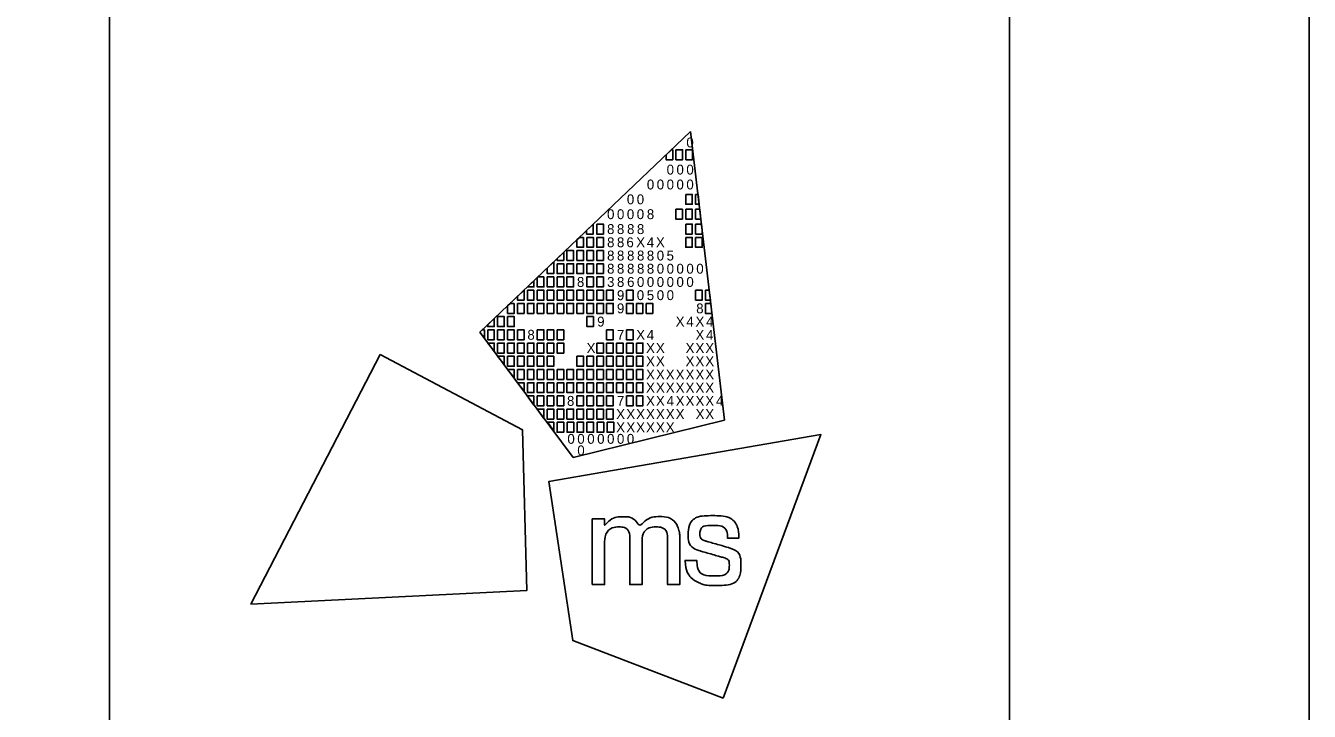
# Model space of a CAD drawing. Extents: x -0.2 to 34, y -2 to 20.
# Drawn here: x 31.86 to 34, y 1.115 to 2.258 of the extents above; entities that cross this region are included whole.
import ezdxf

# ---------------------------------------------------------------- set-up
doc = ezdxf.new("R2010")
doc.units = 0
for name, color, linetype in [('SH_Border', 7, 'Continuous'), ('SH_Cut_Line', 7, 'Continuous'), ('SH_Data', 7, 'Continuous')]:
    doc.layers.add(name, color=color, linetype=linetype)

msp = doc.modelspace()

# ---------------------------------------------------------------- linework, layer by layer
at = {"layer": 'SH_Border'}
msp.add_line((32, -1.5048), (32, 19.4952), dxfattribs=at)
msp.add_lwpolyline([(1.5, 19.4952), (33.5, 19.4952), (33.5, -1.5048), (1.5, -1.5048)], close=True, dxfattribs=at)
at = {"layer": 'SH_Cut_Line'}
msp.add_lwpolyline([(0, -2.0048), (34, -2.0048), (34, 19.9952), (0, 19.9952)], close=True, dxfattribs=at)
at = {"layer": 'SH_Data'}
for p, q in [((32.6175, 1.7471), (32.9688, 2.0813)), ((32.9688, 2.0813), (32.9688, 2.0813)), ((32.9688, 2.0813), (33.0253, 1.6004)), ((32.773, 1.5382), (32.6175, 1.7471)), ((33.0253, 1.6004), (32.773, 1.5382)), ((32.75, 1.4952), (32.75, 1.4952))]:
    msp.add_line(p, q, dxfattribs=at)
for points in [[(32.9279, 2.0424), (32.9369, 2.051), (32.9389, 2.051), (32.9389, 2.0345), (32.9279, 2.0345)], [(32.9444, 2.051), (32.9554, 2.051), (32.9554, 2.0345), (32.9444, 2.0345)], [(32.9609, 2.051), (32.9719, 2.051), (32.9719, 2.0345), (32.9609, 2.0345)], [(32.9606, 1.9767), (32.9716, 1.9767), (32.9716, 1.9602), (32.9606, 1.9602)], [(32.9771, 1.9767), (32.9811, 1.9767), (32.983, 1.9602), (32.9771, 1.9602)], [(32.9441, 1.9519), (32.9551, 1.9519), (32.9551, 1.9354), (32.9441, 1.9354)], [(32.9606, 1.9519), (32.9716, 1.9519), (32.9716, 1.9354), (32.9606, 1.9354)], [(32.9771, 1.9519), (32.984, 1.9519), (32.9859, 1.9354), (32.9771, 1.9354)], [(32.7953, 1.9163), (32.8064, 1.9268), (32.8064, 1.9106), (32.7953, 1.9106)], [(32.8123, 1.9271), (32.8233, 1.9271), (32.8233, 1.9106), (32.8123, 1.9106)], [(32.9606, 1.9271), (32.9716, 1.9271), (32.9716, 1.9106), (32.9606, 1.9106)], [(32.9771, 1.9271), (32.9869, 1.9271), (32.9881, 1.917), (32.9881, 1.9106), (32.9771, 1.9106)], [(32.7958, 1.9051), (32.8068, 1.9051), (32.8068, 1.8886), (32.7958, 1.8886)], [(32.8123, 1.9051), (32.8233, 1.9051), (32.8233, 1.8886), (32.8123, 1.8886)], [(32.9606, 1.9051), (32.9716, 1.9051), (32.9716, 1.8886), (32.9606, 1.8886)], [(32.9771, 1.9051), (32.9881, 1.9051), (32.9881, 1.8886), (32.9771, 1.8886)], [(32.7627, 1.8831), (32.7737, 1.8831), (32.7737, 1.8666), (32.7627, 1.8666)], [(32.7793, 1.8831), (32.7903, 1.8831), (32.7903, 1.8666), (32.7793, 1.8666)], [(32.7958, 1.8831), (32.8068, 1.8831), (32.8068, 1.8666), (32.7958, 1.8666)], [(32.8123, 1.8831), (32.8233, 1.8831), (32.8233, 1.8666), (32.8123, 1.8666)], [(32.7462, 1.8611), (32.7572, 1.8611), (32.7572, 1.8446), (32.7462, 1.8446)], [(32.7627, 1.8611), (32.7737, 1.8611), (32.7737, 1.8446), (32.7627, 1.8446)], [(32.7793, 1.8611), (32.7903, 1.8611), (32.7903, 1.8446), (32.7793, 1.8446)], [(32.7958, 1.8611), (32.8068, 1.8611), (32.8068, 1.8446), (32.7958, 1.8446)], [(32.8123, 1.8611), (32.8233, 1.8611), (32.8233, 1.8446), (32.8123, 1.8446)], [(32.7297, 1.8391), (32.7407, 1.8391), (32.7407, 1.8225), (32.7297, 1.8225)], [(32.7462, 1.8391), (32.7572, 1.8391), (32.7572, 1.8225), (32.7462, 1.8225)], [(32.7627, 1.8391), (32.7737, 1.8391), (32.7737, 1.8225), (32.7627, 1.8225)], [(32.7958, 1.8391), (32.8068, 1.8391), (32.8068, 1.8225), (32.7958, 1.8225)], [(32.8123, 1.8391), (32.8233, 1.8391), (32.8233, 1.8225), (32.8123, 1.8225)], [(32.6967, 1.817), (32.7077, 1.817), (32.7077, 1.8005), (32.6967, 1.8005)], [(32.7132, 1.817), (32.7242, 1.817), (32.7242, 1.8005), (32.7132, 1.8005)], [(32.7297, 1.817), (32.7407, 1.817), (32.7407, 1.8005), (32.7297, 1.8005)], [(32.7462, 1.817), (32.7572, 1.817), (32.7572, 1.8005), (32.7462, 1.8005)], [(32.7627, 1.817), (32.7737, 1.817), (32.7737, 1.8005), (32.7627, 1.8005)], [(32.7793, 1.817), (32.7903, 1.817), (32.7903, 1.8005), (32.7793, 1.8005)], [(32.7958, 1.817), (32.8068, 1.817), (32.8068, 1.8005), (32.7958, 1.8005)], [(32.8123, 1.817), (32.8233, 1.817), (32.8233, 1.8005), (32.8123, 1.8005)], [(32.8288, 1.817), (32.8398, 1.817), (32.8398, 1.8005), (32.8288, 1.8005)], [(32.8618, 1.817), (32.8728, 1.817), (32.8728, 1.8005), (32.8618, 1.8005)], [(32.9771, 1.817), (32.9881, 1.817), (32.9881, 1.8005), (32.9771, 1.8005)], [(32.9935, 1.817), (32.9998, 1.817), (33.0018, 1.8005), (32.9935, 1.8005)], [(32.6802, 1.795), (32.6912, 1.795), (32.6912, 1.7785), (32.6802, 1.7785)], [(32.6967, 1.795), (32.7077, 1.795), (32.7077, 1.7785), (32.6967, 1.7785)], [(32.7132, 1.795), (32.7242, 1.795), (32.7242, 1.7785), (32.7132, 1.7785)], [(32.7297, 1.795), (32.7407, 1.795), (32.7407, 1.7785), (32.7297, 1.7785)], [(32.7462, 1.795), (32.7572, 1.795), (32.7572, 1.7785), (32.7462, 1.7785)], [(32.7627, 1.795), (32.7737, 1.795), (32.7737, 1.7785), (32.7627, 1.7785)], [(32.7793, 1.795), (32.7903, 1.795), (32.7903, 1.7785), (32.7793, 1.7785)], [(32.7958, 1.795), (32.8068, 1.795), (32.8068, 1.7785), (32.7958, 1.7785)], [(32.8123, 1.795), (32.8233, 1.795), (32.8233, 1.7785), (32.8123, 1.7785)], [(32.8288, 1.795), (32.8398, 1.795), (32.8398, 1.7785), (32.8288, 1.7785)], [(32.8618, 1.795), (32.8728, 1.795), (32.8728, 1.7785), (32.8618, 1.7785)], [(32.8783, 1.795), (32.8893, 1.795), (32.8893, 1.7785), (32.8783, 1.7785)], [(32.8947, 1.795), (32.9057, 1.795), (32.9057, 1.7785), (32.8947, 1.7785)], [(32.9935, 1.795), (33.0024, 1.795), (33.0044, 1.7785), (32.9935, 1.7785)], [(32.6471, 1.773), (32.6581, 1.773), (32.6581, 1.7565), (32.6471, 1.7565)], [(32.6637, 1.773), (32.6747, 1.773), (32.6747, 1.7565), (32.6637, 1.7565)], [(32.7958, 1.773), (32.8068, 1.773), (32.8068, 1.7565), (32.7958, 1.7565)], [(32.6306, 1.751), (32.6416, 1.751), (32.6416, 1.7345), (32.6306, 1.7345)], [(32.6471, 1.751), (32.6581, 1.751), (32.6581, 1.7345), (32.6471, 1.7345)], [(32.6637, 1.751), (32.6747, 1.751), (32.6747, 1.7345), (32.6637, 1.7345)], [(32.6802, 1.751), (32.6912, 1.751), (32.6912, 1.7345), (32.6802, 1.7345)], [(32.7132, 1.751), (32.7242, 1.751), (32.7242, 1.7345), (32.7132, 1.7345)], [(32.7297, 1.751), (32.7407, 1.751), (32.7407, 1.7345), (32.7297, 1.7345)], [(32.7462, 1.751), (32.7572, 1.751), (32.7572, 1.7345), (32.7462, 1.7345)], [(32.8288, 1.751), (32.8398, 1.751), (32.8398, 1.7345), (32.8288, 1.7345)], [(32.8618, 1.751), (32.8728, 1.751), (32.8728, 1.7345), (32.8618, 1.7345)], [(32.6306, 1.729), (32.6416, 1.729), (32.6416, 1.7152)], [(32.6471, 1.729), (32.6581, 1.729), (32.6581, 1.7124), (32.6471, 1.7124)], [(32.6637, 1.729), (32.6747, 1.729), (32.6747, 1.7124), (32.6637, 1.7124)], [(32.6802, 1.729), (32.6912, 1.729), (32.6912, 1.7124), (32.6802, 1.7124)], [(32.6967, 1.729), (32.7077, 1.729), (32.7077, 1.7124), (32.6967, 1.7124)], [(32.7132, 1.729), (32.7242, 1.729), (32.7242, 1.7124), (32.7132, 1.7124)], [(32.7297, 1.729), (32.7407, 1.729), (32.7407, 1.7124), (32.7297, 1.7124)], [(32.7462, 1.729), (32.7572, 1.729), (32.7572, 1.7124), (32.7462, 1.7124)], [(32.8123, 1.729), (32.8233, 1.729), (32.8233, 1.7124), (32.8123, 1.7124)], [(32.8288, 1.729), (32.8398, 1.729), (32.8398, 1.7124), (32.8288, 1.7124)], [(32.8453, 1.729), (32.8563, 1.729), (32.8563, 1.7124), (32.8453, 1.7124)], [(32.8618, 1.729), (32.8728, 1.729), (32.8728, 1.7124), (32.8618, 1.7124)], [(32.8783, 1.729), (32.8893, 1.729), (32.8893, 1.7124), (32.8783, 1.7124)], [(32.6471, 1.7069), (32.6581, 1.7069), (32.6581, 1.6932)], [(32.6637, 1.7069), (32.6747, 1.7069), (32.6747, 1.6904), (32.6637, 1.6904)], [(32.6802, 1.7069), (32.6912, 1.7069), (32.6912, 1.6904), (32.6802, 1.6904)], [(32.6967, 1.7069), (32.7077, 1.7069), (32.7077, 1.6904), (32.6967, 1.6904)], [(32.7132, 1.7069), (32.7242, 1.7069), (32.7242, 1.6904), (32.7132, 1.6904)], [(32.7297, 1.7069), (32.7407, 1.7069), (32.7407, 1.6904), (32.7297, 1.6904)], [(32.7793, 1.7069), (32.7903, 1.7069), (32.7903, 1.6904), (32.7793, 1.6904)], [(32.7958, 1.7069), (32.8068, 1.7069), (32.8068, 1.6904), (32.7958, 1.6904)], [(32.8123, 1.7069), (32.8233, 1.7069), (32.8233, 1.6904), (32.8123, 1.6904)], [(32.8288, 1.7069), (32.8398, 1.7069), (32.8398, 1.6904), (32.8288, 1.6904)], [(32.8453, 1.7069), (32.8563, 1.7069), (32.8563, 1.6904), (32.8453, 1.6904)], [(32.8618, 1.7069), (32.8728, 1.7069), (32.8728, 1.6904), (32.8618, 1.6904)], [(32.8783, 1.7069), (32.8893, 1.7069), (32.8893, 1.6904), (32.8783, 1.6904)], [(32.6637, 1.6849), (32.6747, 1.6849), (32.6747, 1.6712)], [(32.6747, 1.6849), (32.6747, 1.6849), (32.6747, 1.6849)], [(32.6802, 1.6849), (32.6912, 1.6849), (32.6912, 1.6684), (32.6802, 1.6684)], [(32.6967, 1.6849), (32.7077, 1.6849), (32.7077, 1.6684), (32.6967, 1.6684)], [(32.7132, 1.6849), (32.7242, 1.6849), (32.7242, 1.6684), (32.7132, 1.6684)], [(32.7297, 1.6849), (32.7407, 1.6849), (32.7407, 1.6684), (32.7297, 1.6684)], [(32.7462, 1.6849), (32.7572, 1.6849), (32.7572, 1.6684), (32.7462, 1.6684)], [(32.7627, 1.6849), (32.7737, 1.6849), (32.7737, 1.6684), (32.7627, 1.6684)], [(32.7793, 1.6849), (32.7903, 1.6849), (32.7903, 1.6684), (32.7793, 1.6684)], [(32.7958, 1.6849), (32.8068, 1.6849), (32.8068, 1.6684), (32.7958, 1.6684)], [(32.8123, 1.6849), (32.8233, 1.6849), (32.8233, 1.6684), (32.8123, 1.6684)], [(32.8288, 1.6849), (32.8398, 1.6849), (32.8398, 1.6684), (32.8288, 1.6684)], [(32.8453, 1.6849), (32.8563, 1.6849), (32.8563, 1.6684), (32.8453, 1.6684)], [(32.8618, 1.6849), (32.8728, 1.6849), (32.8728, 1.6684), (32.8618, 1.6684)], [(32.8783, 1.6849), (32.8893, 1.6849), (32.8893, 1.6684), (32.8783, 1.6684)], [(32.6802, 1.6629), (32.6912, 1.6629), (32.6912, 1.6491)], [(32.6967, 1.6629), (32.7077, 1.6629), (32.7077, 1.6464), (32.6967, 1.6464)], [(32.7132, 1.6629), (32.7242, 1.6629), (32.7242, 1.6464), (32.7132, 1.6464)], [(32.7297, 1.6629), (32.7407, 1.6629), (32.7407, 1.6464), (32.7297, 1.6464)], [(32.7462, 1.6629), (32.7572, 1.6629), (32.7572, 1.6464), (32.7462, 1.6464)], [(32.7627, 1.6629), (32.7737, 1.6629), (32.7737, 1.6464), (32.7627, 1.6464)], [(32.7793, 1.6629), (32.7903, 1.6629), (32.7903, 1.6464), (32.7793, 1.6464)], [(32.7958, 1.6629), (32.8068, 1.6629), (32.8068, 1.6464), (32.7958, 1.6464)], [(32.8123, 1.6629), (32.8233, 1.6629), (32.8233, 1.6464), (32.8123, 1.6464)], [(32.8288, 1.6629), (32.8398, 1.6629), (32.8398, 1.6464), (32.8288, 1.6464)], [(32.8453, 1.6629), (32.8563, 1.6629), (32.8563, 1.6464), (32.8453, 1.6464)], [(32.8618, 1.6629), (32.8728, 1.6629), (32.8728, 1.6464), (32.8618, 1.6464)], [(32.8783, 1.6629), (32.8893, 1.6629), (32.8893, 1.6464), (32.8783, 1.6464)], [(32.7077, 1.6257), (32.6965, 1.6409), (32.7077, 1.6409)], [(32.7132, 1.6409), (32.7242, 1.6409), (32.7242, 1.6244), (32.7132, 1.6244)], [(32.7297, 1.6409), (32.7407, 1.6409), (32.7407, 1.6244), (32.7297, 1.6244)], [(32.7462, 1.6409), (32.7572, 1.6409), (32.7572, 1.6244), (32.7462, 1.6244)], [(32.7793, 1.6409), (32.7903, 1.6409), (32.7903, 1.6244), (32.7793, 1.6244)], [(32.7958, 1.6409), (32.8068, 1.6409), (32.8068, 1.6244), (32.7958, 1.6244)], [(32.8123, 1.6409), (32.8233, 1.6409), (32.8233, 1.6244), (32.8123, 1.6244)], [(32.8288, 1.6409), (32.8398, 1.6409), (32.8398, 1.6244), (32.8288, 1.6244)], [(32.8618, 1.6409), (32.8728, 1.6409), (32.8728, 1.6244), (32.8618, 1.6244)], [(32.8783, 1.6409), (32.8893, 1.6409), (32.8893, 1.6244), (32.8783, 1.6244)], [(32.724, 1.6034), (32.7132, 1.6189), (32.7242, 1.6189)], [(32.7297, 1.6189), (32.7407, 1.6189), (32.7407, 1.6024), (32.7297, 1.6024)], [(32.7462, 1.6189), (32.7572, 1.6189), (32.7572, 1.6024), (32.7462, 1.6024)], [(32.7627, 1.6189), (32.7737, 1.6189), (32.7737, 1.6024), (32.7627, 1.6024)], [(32.7793, 1.6189), (32.7903, 1.6189), (32.7903, 1.6024), (32.7793, 1.6024)], [(32.7958, 1.6189), (32.8068, 1.6189), (32.8068, 1.6024), (32.7958, 1.6024)], [(32.8123, 1.6189), (32.8233, 1.6189), (32.8233, 1.6024), (32.8123, 1.6024)], [(32.8288, 1.6189), (32.8398, 1.6189), (32.8398, 1.6024), (32.8288, 1.6024)], [(32.7302, 1.5969), (32.7407, 1.5969), (32.7408, 1.5827)], [(32.7463, 1.5969), (32.7573, 1.5969), (32.7573, 1.5804), (32.7463, 1.5804)], [(32.763, 1.5969), (32.774, 1.5969), (32.774, 1.5804), (32.763, 1.5804)], [(32.7794, 1.5969), (32.7904, 1.5969), (32.7904, 1.5804), (32.7794, 1.5804)], [(32.796, 1.5969), (32.807, 1.5969), (32.807, 1.5804), (32.796, 1.5804)], [(32.8129, 1.5969), (32.8239, 1.5969), (32.8239, 1.5803), (32.8129, 1.5803)], [(32.8296, 1.5969), (32.8406, 1.5969), (32.8406, 1.5803), (32.8296, 1.5803)]]:
    msp.add_lwpolyline(points, close=True, dxfattribs=at)
for points in [[(32.7903, 1.9051), (32.7836, 1.9051), (32.7793, 1.901), (32.7793, 1.8886), (32.7903, 1.8886), (32.7903, 1.9051)], [(32.7407, 1.8643), (32.7297, 1.8539), (32.7297, 1.8446), (32.7407, 1.8446), (32.7407, 1.8643)], [(32.7572, 1.88), (32.7462, 1.8696), (32.7462, 1.8666), (32.7572, 1.8666), (32.7572, 1.88)], [(32.7077, 1.8329), (32.6968, 1.8225), (32.7077, 1.8225), (32.7077, 1.8329)], [(32.7242, 1.8391), (32.7141, 1.8391), (32.7132, 1.8382), (32.7132, 1.8225), (32.7242, 1.8225), (32.7242, 1.8391)], [(32.6912, 1.8172), (32.6802, 1.8067), (32.6802, 1.8005), (32.6912, 1.8005), (32.6912, 1.8172)], [(32.6747, 1.795), (32.6679, 1.795), (32.6637, 1.791), (32.6637, 1.7785), (32.6747, 1.7785), (32.6747, 1.795)], [(32.6416, 1.7701), (32.6306, 1.7596), (32.6306, 1.7565), (32.6416, 1.7565), (32.6416, 1.7701)], [(32.6251, 1.751), (32.6216, 1.751), (32.6175, 1.7471), (32.6251, 1.7369), (32.6251, 1.751)], [(32.4512, 1.7101), (32.2359, 1.294), (32.6956, 1.3167), (32.6884, 1.5844), (32.4512, 1.7101)], [(33.0229, 1.1374), (33.1859, 1.5766), (32.7324, 1.4981), (32.7722, 1.2333), (33.0229, 1.1374)]]:
    msp.add_lwpolyline(points, dxfattribs=at)
for points in [[(32.8048, 1.3267), (32.8048, 1.3267), (32.8048, 1.4361), (32.8048, 1.4361), (32.8048, 1.4361), (32.8255, 1.4361), (32.8255, 1.4361), (32.8255, 1.4361), (32.8255, 1.4249), (32.8255, 1.4249), (32.8346, 1.4351), (32.8457, 1.4397), (32.8555, 1.4397), (32.8688, 1.4397), (32.8791, 1.4324), (32.8837, 1.4218), (32.8915, 1.4333), (32.905, 1.4398), (32.9166, 1.4398), (32.9325, 1.4398), (32.9451, 1.4302), (32.9494, 1.4165), (32.9494, 1.4164), (32.9494, 1.4164), (32.9494, 1.4163), (32.9501, 1.4142), (32.9506, 1.4124), (32.9506, 1.4023), (32.9506, 1.4023), (32.9506, 1.3266), (32.9506, 1.3266), (32.9506, 1.3266), (32.9303, 1.3266), (32.9303, 1.3266), (32.9303, 1.3266), (32.9303, 1.4), (32.9303, 1.4), (32.9303, 1.4153), (32.9219, 1.4226), (32.911, 1.4226), (32.8995, 1.4226), (32.8879, 1.4123), (32.8879, 1.3953), (32.8879, 1.3953), (32.8879, 1.3267), (32.8879, 1.3267), (32.8879, 1.3267), (32.8674, 1.3267), (32.8674, 1.3267), (32.8674, 1.3267), (32.8674, 1.4011), (32.8674, 1.4011), (32.8674, 1.4155), (32.8588, 1.4226), (32.8496, 1.4226), (32.8384, 1.4226), (32.8254, 1.4122), (32.8254, 1.3914), (32.8254, 1.3914), (32.8254, 1.3267), (32.8254, 1.3267), (32.8254, 1.3267), (32.8048, 1.3267), (32.8048, 1.3267)], [(32.9595, 1.3661), (32.9595, 1.3661), (32.9595, 1.3669), (32.9595, 1.3669), (32.9595, 1.3669), (32.9603, 1.3669), (32.9603, 1.3669), (32.9603, 1.3669), (32.9783, 1.3669), (32.9783, 1.3669), (32.9783, 1.3669), (32.9789, 1.3669), (32.9789, 1.3669), (32.9789, 1.3669), (32.979, 1.3662), (32.979, 1.3662), (32.9803, 1.3506), (32.9887, 1.3412), (33.009, 1.3412), (33.0273, 1.3412), (33.0333, 1.3506), (33.0333, 1.3583), (33.0333, 1.3684), (33.0256, 1.371), (33.0175, 1.3732), (33.0175, 1.3732), (32.987, 1.3819), (32.987, 1.3819), (32.972, 1.3861), (32.9648, 1.3971), (32.9648, 1.4094), (32.9648, 1.4255), (32.9768, 1.4414), (33.0052, 1.4414), (33.0348, 1.4414), (33.0489, 1.4237), (33.0489, 1.4047), (33.0489, 1.4047), (33.0489, 1.4039), (33.0489, 1.4039), (33.0489, 1.4039), (33.0482, 1.4039), (33.0482, 1.4039), (33.0482, 1.4039), (33.0312, 1.4039), (33.0312, 1.4039), (33.0312, 1.4039), (33.0305, 1.4039), (33.0305, 1.4039), (33.0305, 1.4039), (33.0305, 1.4046), (33.0305, 1.4046), (33.0301, 1.416), (33.0226, 1.4252), (33.0056, 1.4252), (32.9891, 1.4252), (32.9843, 1.417), (32.9843, 1.4109), (32.9843, 1.406), (32.9869, 1.4011), (32.9959, 1.3985), (32.9959, 1.3985), (33.0255, 1.39), (33.0255, 1.39), (33.0462, 1.3841), (33.0527, 1.3729), (33.0527, 1.3591), (33.0527, 1.3414), (33.041, 1.325), (33.0087, 1.325), (32.9952, 1.325), (32.9877, 1.3273), (32.9823, 1.33), (32.969, 1.3366), (32.9609, 1.3488), (32.9595, 1.3661)]]:
    msp.add_open_spline(points, degree=3, dxfattribs=at)

# ---------------------------------------------------------------- texts
for s, p in [('0', (32.9617, 2.0549)), ('0', (32.9288, 2.0097)), ('0', (32.9452, 2.0097)), ('0', (32.9617, 2.0097)), ('0', (32.8958, 1.9849)), ('0', (32.9123, 1.9849)), ('0', (32.9288, 1.9849)), ('0', (32.9452, 1.9849)), ('0', (32.9617, 1.9849)), ('0', (32.8625, 1.9602)), ('0', (32.879, 1.9602)), ('0', (32.8295, 1.9354)), ('0', (32.846, 1.9354)), ('0', (32.8625, 1.9354)), ('0', (32.879, 1.9354)), ('8', (32.8958, 1.9354)), ('8', (32.8295, 1.9106)), ('8', (32.846, 1.9106)), ('8', (32.8628, 1.9106)), ('8', (32.8793, 1.9106)), ('8', (32.8295, 1.8886)), ('8', (32.846, 1.8886)), ('6', (32.8618, 1.8886)), ('X', (32.8781, 1.8886)), ('4', (32.8958, 1.8886)), ('X', (32.911, 1.8886)), ('8', (32.8295, 1.8665)), ('8', (32.846, 1.8665)), ('8', (32.8628, 1.8665)), ('8', (32.8794, 1.8665)), ('8', (32.8958, 1.8665)), ('0', (32.9123, 1.8665)), ('5', (32.9287, 1.8665)), ('8', (32.8295, 1.8446)), ('8', (32.846, 1.8446)), ('8', (32.8628, 1.8446)), ('8', (32.8794, 1.8446)), ('8', (32.8958, 1.8446)), ('0', (32.9123, 1.8446)), ('0', (32.9288, 1.8446)), ('0', (32.9452, 1.8446)), ('0', (32.9617, 1.8446)), ('0', (32.9782, 1.8446)), ('8', (32.7793, 1.8225)), ('3', (32.8295, 1.8225)), ('8', (32.846, 1.8225)), ('6', (32.8629, 1.8225)), ('0', (32.8793, 1.8225)), ('0', (32.8958, 1.8225)), ('0', (32.9123, 1.8225)), ('0', (32.9288, 1.8225)), ('0', (32.9452, 1.8225)), ('0', (32.9617, 1.8225)), ('9', (32.846, 1.8005)), ('0', (32.879, 1.8005)), ('5', (32.8957, 1.8005)), ('0', (32.9123, 1.8005)), ('0', (32.9288, 1.8005)), ('9', (32.846, 1.7785)), ('8', (32.9781, 1.7785)), ('9', (32.813, 1.7565)), ('X', (32.9439, 1.7565)), ('4', (32.9617, 1.7565)), ('X', (32.9769, 1.7565)), ('4', (32.9946, 1.7565)), ('8', (32.6967, 1.7345)), ('7', (32.846, 1.7345)), ('X', (32.8781, 1.7345)), ('4', (32.8958, 1.7345)), ('X', (32.9769, 1.7345)), ('4', (32.9946, 1.7345)), ('X', (32.7955, 1.7124)), ('X', (32.8945, 1.7124)), ('X', (32.911, 1.7124)), ('X', (32.9604, 1.7124)), ('X', (32.9769, 1.7124)), ('X', (32.9933, 1.7124)), ('X', (32.8945, 1.6904)), ('X', (32.911, 1.6904)), ('X', (32.9604, 1.6904)), ('X', (32.9769, 1.6904)), ('X', (32.9933, 1.6904)), ('X', (32.8945, 1.6684)), ('X', (32.911, 1.6684)), ('X', (32.9274, 1.6684)), ('X', (32.9439, 1.6684)), ('X', (32.9604, 1.6684)), ('X', (32.9769, 1.6684)), ('X', (32.9933, 1.6684)), ('X', (32.8945, 1.6464)), ('X', (32.911, 1.6464)), ('X', (32.9274, 1.6464)), ('X', (32.9439, 1.6464)), ('X', (32.9604, 1.6464)), ('X', (32.9769, 1.6464)), ('X', (32.9933, 1.6464)), ('8', (32.7627, 1.6244)), ('7', (32.846, 1.6244)), ('X', (32.8945, 1.6244)), ('X', (32.911, 1.6244)), ('4', (32.9288, 1.6244)), ('X', (32.9439, 1.6244)), ('X', (32.9604, 1.6244)), ('X', (32.9769, 1.6244)), ('X', (32.9933, 1.6244)), ('4', (33.0111, 1.6244)), ('X', (32.8447, 1.6024)), ('X', (32.8616, 1.6024)), ('X', (32.878, 1.6024)), ('X', (32.8945, 1.6024)), ('X', (32.911, 1.6024)), ('X', (32.9274, 1.6024)), ('X', (32.9439, 1.6024)), ('X', (32.9771, 1.6024)), ('X', (32.9933, 1.6024)), ('X', (32.8447, 1.5803)), ('X', (32.8616, 1.5803)), ('X', (32.878, 1.5803)), ('X', (32.8945, 1.5803)), ('X', (32.911, 1.5803)), ('X', (32.9274, 1.5803)), ('0', (32.7634, 1.5611)), ('0', (32.7799, 1.5611)), ('0', (32.7965, 1.5611)), ('0', (32.813, 1.5611)), ('0', (32.8295, 1.5611)), ('0', (32.846, 1.5611)), ('0', (32.8625, 1.5611)), ('0', (32.7799, 1.5419))]:
    msp.add_text(s, height=0.0165, rotation=360, dxfattribs=at).set_placement(p)

doc.saveas('drawing.dxf')
